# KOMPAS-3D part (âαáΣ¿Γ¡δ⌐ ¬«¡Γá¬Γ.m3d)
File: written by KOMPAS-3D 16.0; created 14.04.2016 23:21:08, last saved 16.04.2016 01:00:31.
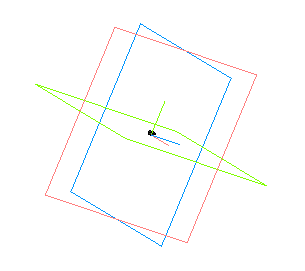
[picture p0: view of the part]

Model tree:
1. Эскиз:1
2. Операция вращения:1
     Угол 1 = 360
3. Скругление:1
     Радиус = 0.5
